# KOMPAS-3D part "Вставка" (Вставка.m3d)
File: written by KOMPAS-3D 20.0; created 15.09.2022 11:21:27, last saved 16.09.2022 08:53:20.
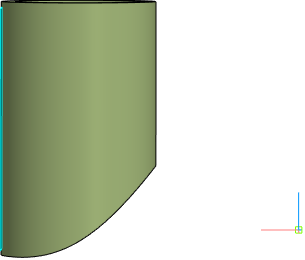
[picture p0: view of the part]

Document properties: Полное имя файла: D:\YAKOVLEV\ПРОЕКТЫ\ДЦ-2. ДП-7 Газопровод Окожушивание\ПРОБА Соединение труб. Окожушивание\ПРОБА 2\Вставка.m3d

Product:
- Part/product: Вставка
    Материал: Сталь 45  ГОСТ 1050-2013 (density 7810 kg/m3)
    Масса: 5221.4

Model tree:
1. Эскиз:1  (with: Смещенная плоскость:1)
2. Обечайка:1
     Расстояние 1 = 1647; Толщина листового тела = 110
3. Сгиб(1) - Обечайка:1
     Радиус сгиба = 500; Коэффициент = 0.4; Величина сгиба = 10; Зазор = 0.01
4. Касательная плоскость:1  (with: Обечайка:1)
5. Фаска:1  (with: Обечайка:1)
     Угол = 45; Длина 1 = 28; Длина 2 = 28
6. Развертка  (labels: Сталь 45  ГОСТ 1050-2013)

Expressions: 900+100
Referenced files in D:\YAKOVLEV\ПРОЕКТЫ\ДЦ-2. ДП-7 Газопровод Окожушивание\ПРОБА Соединение труб. Окожушивание\ПРОБА 2\: Соединение труб.a3d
